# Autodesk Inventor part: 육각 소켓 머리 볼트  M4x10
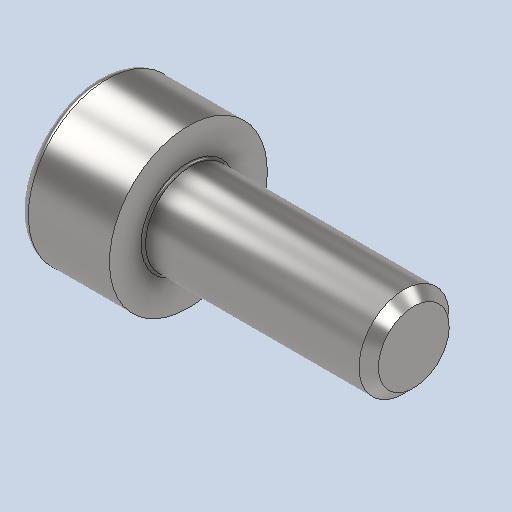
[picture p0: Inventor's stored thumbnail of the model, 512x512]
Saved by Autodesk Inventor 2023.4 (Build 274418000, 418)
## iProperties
Created: 2024-04
Part Number: 육각 소켓 머리 볼트  M4x10
Material: 강철, 연강
Description: 6각머리 태핑 나사
Document SubType Name: Modeling
Designer: Edu03
Density: 7.85 g/cm^3
Appearance: 기본값
Author: jhkim
Sending System: Autodesk Inventor 2025
Preprocessor: ST-DEVELOPER v20
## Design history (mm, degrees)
feature "Solid1"
node "솔리드1"
